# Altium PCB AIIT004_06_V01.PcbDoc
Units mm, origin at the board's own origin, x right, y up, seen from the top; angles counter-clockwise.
Board outline 38.28 x 38.25 mm, 2 copper layers (TopLayer, BottomLayer); 78 components, 44 nets, 236 pads, 151 vias.
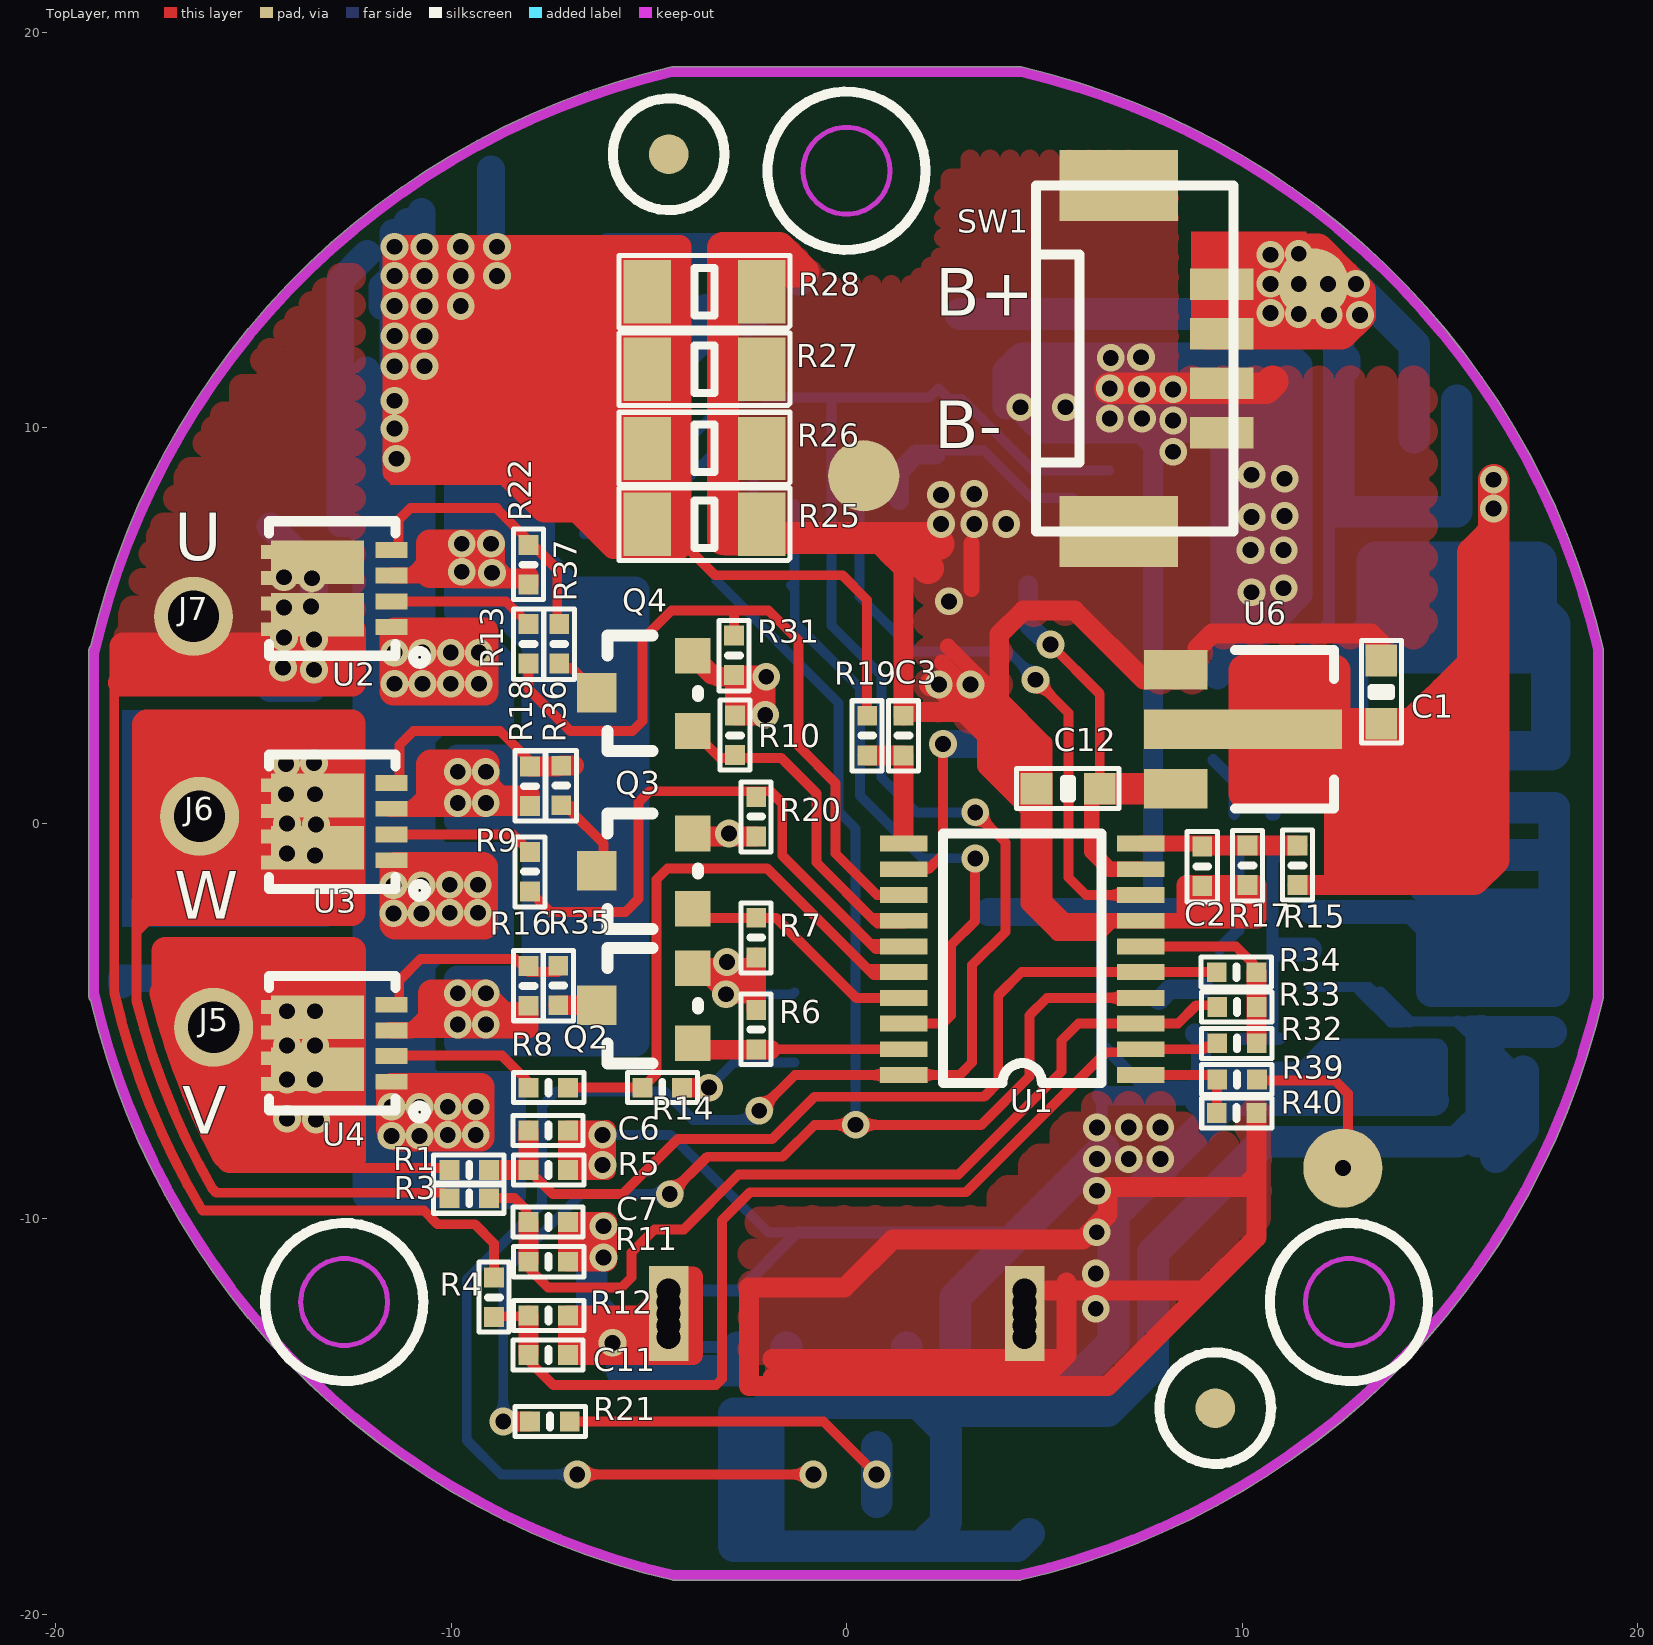
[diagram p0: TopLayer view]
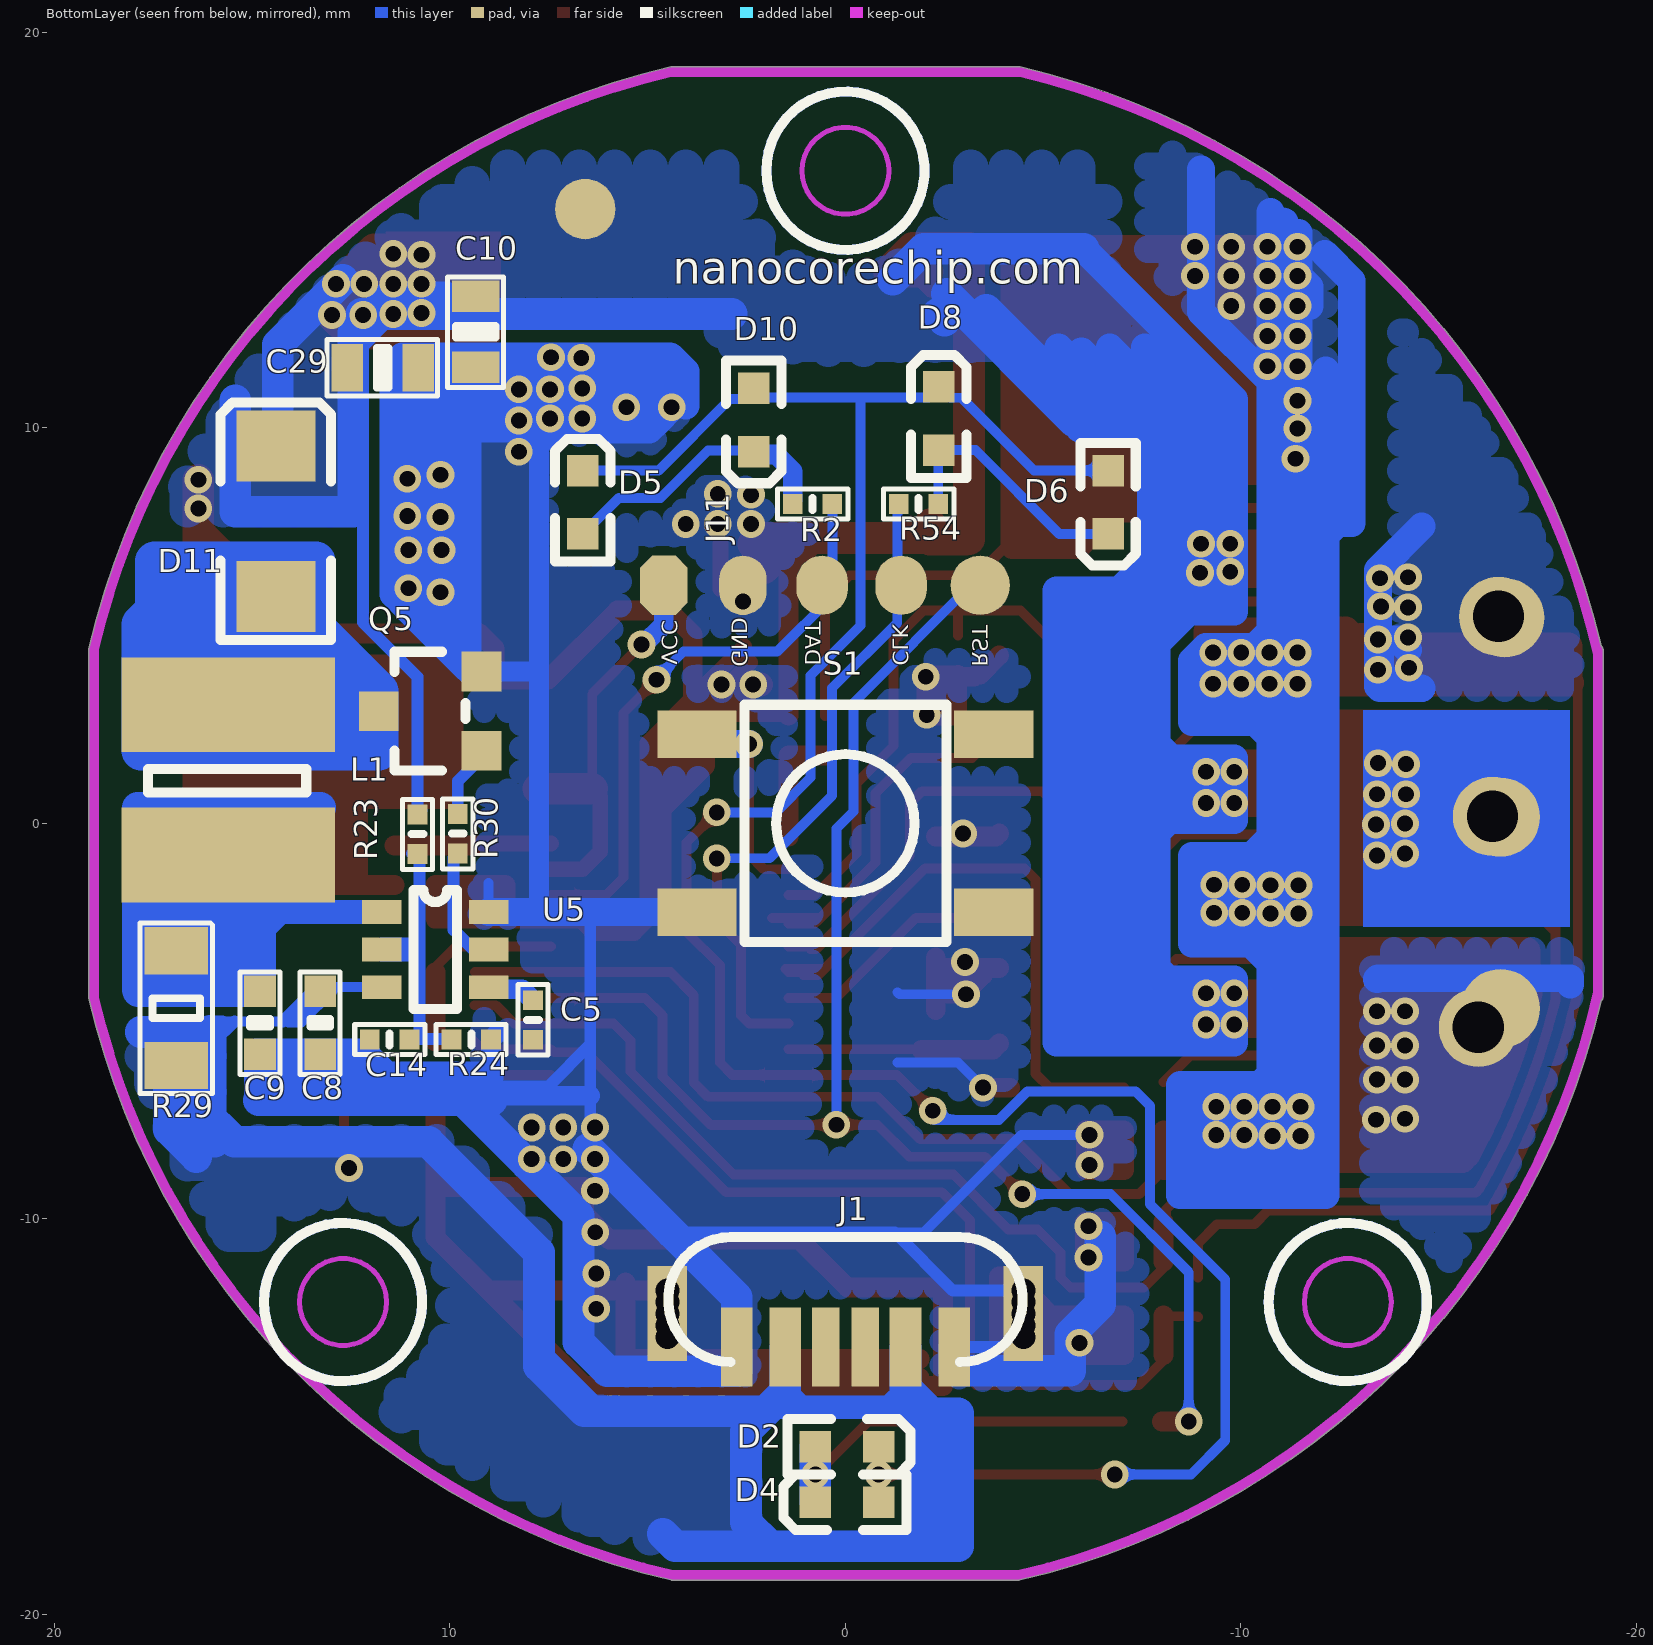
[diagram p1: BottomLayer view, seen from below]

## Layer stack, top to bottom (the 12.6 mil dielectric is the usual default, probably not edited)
TopSolder: solder mask 0.0102, Solder Resist, Dk 3.5
TopLayer: signal copper 0.0356
Dielectric1: dielectric 0.32, FR-4, Dk 4.8
BottomLayer: signal copper 0.0356
BottomSolder: solder mask 0.0102, Solder Resist, Dk 3.5

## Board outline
-19.153,-4.387 -19.153,4.224 cw(c-19.03,4.257) -19.154,4.285 -19.153,4.387 cw(c-19.025,4.387) -19.108,4.483 cw(c0,0) -4.415,19.124 cw(c-4.387,19) -4.379,19.127 4.38,19.127 cw(c4.387,19) 4.415,19.124 cw(c0,0) 19.124,4.415 cw(c19,4.387) 19.128,4.387 19.127,-4.387 cw(c19.001,-4.387) 19.126,-4.405 cw(c19,-4.389) 19.124,-4.417 cw(c0,0) 4.415,-19.124 cw(c4.387,-19) 4.379,-19.127 -4.379,-19.127 cw(c-4.387,-19) -4.415,-19.124 cw(c0,0) -19.108,-4.483 cw(c-19.025,-4.387)

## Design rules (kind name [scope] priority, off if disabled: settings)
Clearance Clearance_1 [All] p1: gap=0.2 ignorepadtopadclearanceinfootprint=FALSE
Clearance [All] p2: gap=0.2 ignorepadtopadclearanceinfootprint=FALSE
ComponentClearance [All] p1 off: gap=0.254 collisioncheckmode=3 verticalgap=0.254 showdistances=FALSE
DiffPairsRouting [All] p1: maxlimit=0.254 minlimit=0.254 mostfreqgap=0.254 substack1={E679878C-6FF9-4B68-BEEA-18ABA4E6F12B} toplayer_{e679878c-6ff9-4b68-beea-18aba4e6f12b}_minwidth=0.381 toplayer_{e679878c-6ff9-4b68-beea-18aba4e6f12b}_maxwidth=0.381 toplayer_{e679878c-6ff9-4b68-beea-18aba4e6f12b}_prefwidth=0.381 bottomlayer_{e679878c-6ff9-4b68-beea-18aba4e6f12b}_minwidth=0.381 bottomlayer_{e679878c-6ff9-4b68-beea-18aba4e6f12b}_maxwidth=0.381 bottomlayer_{e679878c-6ff9-4b68-beea-18aba4e6f12b}_prefwidth=0.381 toplayer_minwidth=0.381 toplayer_maxwidth=0.381 toplayer_prefwidth=0.381 bottomlayer_minwidth=0.381 bottomlayer_maxwidth=0.381 bottomlayer_prefwidth=0.381 substack2={777710C2-B5EE-40DD-8915-E3704981BEB1} toplayer_{777710c2-b5ee-40dd-8915-e3704981beb1}_minwidth=0.381 toplayer_{777710c2-b5ee-40dd-8915-e3704981beb1}_maxwidth=0.381 toplayer_{777710c2-b5ee-40dd-8915-e3704981beb1}_prefwidth=0.381 bottomlayer_{777710c2-b5ee-40dd-8915-e3704981beb1}_minwidth=0.381 bottomlayer_{777710c2-b5ee-40dd-8915-e3704981beb1}_maxwidth=0.381 bottomlayer_{777710c2-b5ee-40dd-8915-e3704981beb1}_prefwidth=0.381 substack3={E62929A6-BD46-4539-BCB2-BD57CF14018D} toplayer_{e62929a6-bd46-4539-bcb2-bd57cf14018d}_minwidth=0.381 toplayer_{e62929a6-bd46-4539-bcb2-bd57cf14018d}_maxwidth=0.381 toplayer_{e62929a6-bd46-4539-bcb2-bd57cf14018d}_prefwidth=0.381 bottomlayer_{e62929a6-bd46-4539-bcb2-bd57cf14018d}_minwidth=0.381 bottomlayer_{e62929a6-bd46-4539-bcb2-bd57cf14018d}_maxwidth=0.381 bottomlayer_{e62929a6-bd46-4539-bcb2-bd57cf14018d}_prefwidth=0.381 substack4={0F8194CC-C03F-4DEF-AB20-F6559DEB5A2B} toplayer_{0f8194cc-c03f-4def-ab20-f6559deb5a2b}_minwidth=0.381 toplayer_{0f8194cc-c03f-4def-ab20-f6559deb5a2b}_maxwidth=0.381 toplayer_{0f8194cc-c03f-4def-ab20-f6559deb5a2b}_prefwidth=0.381 bottomlayer_{0f8194cc-c03f-4def-ab20-f6559deb5a2b}_minwidth=0.381 bottomlayer_{0f8194cc-c03f-4def-ab20-f6559deb5a2b}_maxwidth=0.381 bottomlayer_{0f8194cc-c03f-4def-ab20-f6559deb5a2b}_prefwidth=0.381 substack5={8A69428B-D5D5-4660-97CD-E7EB869ACB37} toplayer_{8a69428b-d5d5-4660-97cd-e7eb869acb37}_minwidth=0.381 toplayer_{8a69428b-d5d5-4660-97cd-e7eb869acb37}_maxwidth=0.381 toplayer_{8a69428b-d5d5-4660-97cd-e7eb869acb37}_prefwidth=0.381 bottomlayer_{8a69428b-d5d5-4660-97cd-e7eb869acb37}_minwidth=0.381 bottomlayer_{8a69428b-d5d5-4660-97cd-e7eb869acb37}_maxwidth=0.381 bottomlayer_{8a69428b-d5d5-4660-97cd-e7eb869acb37}_prefwidth=0.381 maxuncoupledlength=12.7
FabricationTestPointUsage TestPointUsage [All] p1: valid=0 allowmultiple=FALSE
FabricationTestpoint Testpoint [All] p1: side=3 testpointundercomponent=TRUE minsize=1.016 maxsize=2.54 preferedsize=1.524 minholesize=0.508 maxholesize=1.016 preferedholesize=0.813 testpointgrid=0.025 allowsidetop=TRUE allowsidebottom=TRUE usegrid=TRUE gridtolerance=0
Height [All] p1 off: minheight=0 maxheight=25.4 prefheight=12.7
PolygonConnect [All] p1: connectstyle=Direct reliefconductorwidth=0.254 reliefentries=4 polygonreliefangle="90 Angle" airgapwidth=0.254
RoutingVias [All] p1: holewidth=0.711 width=1.27 viastyle="Through Hole" minholewidth=0.711 minwidth=1.27 maxholewidth=0.711 maxwidth=1.27
SolderMaskExpansion [All] p1: expansion=0.102 istentingtop=FALSE
Width [All] p1: maxlimit=8 minlimit=0.25 preferedwidth=0.8 substack1={E679878C-6FF9-4B68-BEEA-18ABA4E6F12B} substack2={777710C2-B5EE-40DD-8915-E3704981BEB1} substack3={E62929A6-BD46-4539-BCB2-BD57CF14018D} substack4={0F8194CC-C03F-4DEF-AB20-F6559DEB5A2B} substack5={8A69428B-D5D5-4660-97CD-E7EB869ACB37}
25 further rules are at their usual default settings.

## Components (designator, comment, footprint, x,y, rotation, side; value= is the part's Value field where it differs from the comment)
C1 "104" 0603M 13.52,4.12 r0 top
C2 "104" 0402M 8.992,-0.584 r0 top
C3 "102" 0402M 1.44,2.72 r0 top
C5 "105" 0402M 7.899,-5.47 r0 bottom
C6 "NC" 0402M -7.04,-7.76 r270 top
C7 "NC" 0402M -7.04,-10.08 r270 top
C8 "106" 0603M 13.28,-5.84 r0 bottom
C9 "106" 0603M 14.8,-5.84 r0 bottom
C10 "10uF" 0805MS 9.35,11.53 r0 bottom
C11 "NC" 0402M -7.04,-13.44 r270 top
C12 "106" 0603M 4.8,0.88 r90 top
C14 "100pF" 0402M 12.024,-5.461 r90 bottom
C29 "10uF" 0805MS 12.598,11.52 r90 bottom
D2 "GREEN" SMD_LED_0603 -0.04,-15.76 r180 bottom
D4 "RLED" SMD_LED_0603 -0.04,-17.16 r0 bottom
D5 "GREEN" SMD_LED_0603 6.64,8.12 r90 bottom locked
D6 "GREEN" SMD_LED_0603 -6.64,8.12 r270 bottom locked
D8 "GREEN" SMD_LED_0603 -2.362,10.236 r90 bottom
D10 "GREEN" SMD_LED_0603 2.32,10.2 r270 bottom
D11 "SS34" SMA 14.4,7.64 r90 bottom
J1 "TYPE-C" TYPE-C-CV 0,-12.04 r90 bottom
J5 "W" TP1 -16.002,-5.156 r0 top
J6 "V" TP1 -16.358,0.178 r0 top
J7 "U" TP1 -16.51,5.232 r0 top
J11 "con16" SIP6-2.0 4.591,6.02 r180 bottom
L1 "4.7UH" L_CD58 15.6,-0.8 r0 bottom
Q2 "2N7002" SOT-23 -3.886,-5.563 r90 top
Q3 "2N7002" SOT-23 -3.886,-2.159 r90 top
Q4 "2N7002" SOT-23 -3.886,2.337 r90 top
Q5 "KS3400" SOT23L 11.8,2.84 r180 bottom
R1 "6.2K" 0402M -9.04,-8.76 r270 top
R2 "1K" 0402M 1.33,8.077 r90 bottom
R3 "6.2K" 0402M -9.04,-9.474 r270 top
R4 "6.2K" 0402M -8.915,-12.481 r180 top
R5 "1K" 0402M -8.04,-8.76 r90 top
R6 "5.1K" 0402M -2.286,-5.715 r180 top
R7 "5.1K" 0402M -2.286,-2.388 r0 top
R8 "47R" 0402M -8.04,-6.68 r90 top
R9 "47R" 0402M -8,-0.72 r0 top
R10 "5.1K" 0402M -2.819,1.727 r180 top
R11 "1K" 0402M -8.04,-11.08 r90 top
R12 "1K" 0402M -8.04,-12.44 r90 top
R13 "47R" 0402M -8.04,5.04 r0 top
R14 "5.1K" 0402M -5.16,-6.68 r90 top
R15 "1M" 0402M 11.4,-1.56 r180 top
R16 "5.1K" 0402M -8.04,-4.608 r180 top
R17 "100K" 0402M 10.135,-0.559 r0 top
R18 "5.1K" 0402M -8,0.44 r180 top
R19 "1K" 0402M 0.52,2.72 r0 top
R20 "5.1K" 0402M -2.286,0.67 r0 top
R21 "1K" 0402M -8,-15.12 r90 top
R22 "5.1K" 0402M -8.04,6.04 r180 top
R23 "953K" 0402M 10.82,0.229 r180 bottom
R24 "100K" 0402M 8.957,-5.461 r270 bottom
R25 "0.1" 1206M -5.04,7.56 r0 top
R26 "0.1" 1206M -5.04,9.48 r0 top
R27 "0.1" 1206M -5.04,11.48 r0 top
R28 "0.1" 1206M -5.04,13.44 r0 top
R29 "0.1" 1206M 16.92,-6.12 r90 bottom
R30 "47R" 0402M 9.8,0.24 r180 bottom
R31 "5.1K" 0402M -2.845,4.75 r0 top
R32 "6.2K" 0402M 10.37,-5.56 r270 top
R33 "6.2K" 0402M 10.37,-4.64 r270 top
R34 "6.2K" 0402M 10.36,-3.76 r270 top
R35 "47R" 0402M -7.29,-3.597 r0 top
R36 "47R" 0402M -7.214,1.457 r0 top
R37 "47R" 0402M -7.264,5.04 r0 top
R39 "1K" 0402M 10.373,-6.477 r270 top
R40 "5.1K" 0402M 9.36,-7.32 r90 top
R54 "1K" 0402M -1.346,8.077 r90 bottom
S1 "SW-PB" 6MM-BTNSMD 0,0 r180 bottom locked
SW1 "DP_1*5" CH1.25_4PVH 9.483,13.629 r270 top
U1 "ATM8F8040" SSOP20 7.64,-6.36 r180 top
U2 "KS3640" DFN-8_3333 -13.031,5.911 r90 top
U3 "KS3640" DFN-8_3333 -13.031,0.018 r90 top
U4 "KS3640" DFN-8_3333 -13.031,-5.585 r90 top
U5 "CN3300" SOT23-6 11.72,-2.24 r180 bottom
U6 "HT7550" SOT89 8.32,3.88 r270 top

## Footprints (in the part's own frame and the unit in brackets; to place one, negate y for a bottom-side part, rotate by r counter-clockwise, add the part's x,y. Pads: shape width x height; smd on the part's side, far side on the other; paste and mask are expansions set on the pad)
6MM-BTNSMD [mm]
  rect 2x1.2 smd: 1(-3.75,2.25) 2(-3.75,-2.25) 3(3.75,-2.25) 4(3.75,2.25)
  silkscreen extent -2.55,-3 2.55,3
0402M [mm]
  rect 0.5x0.5 smd: 1(0,0) 2(0,-1)
  silkscreen extent -0.38,-1.4 0.38,0.38
0603M [mm]
  rect 0.8x0.8 smd: 1(0,0) 2(0,-1.6)
  silkscreen extent -0.51,-2.08 0.51,0.51
0805MS [mm]
  rect 1.2x0.8 smd: 1(0,0) 2(0,-1.8)
  silkscreen extent -0.71,-2.29 0.71,0.51
1206M [mm]
  rect 1.2x1.6 smd: 1(0,0) 2(2.9,0)
  silkscreen extent -0.71,-0.91 3.61,0.91
CH1.25_4PVH [mm]
  rect 1.8x3 smd: 0(-2.5,-2.6) 0(6.25,-2.6)
  rect 0.8x1.6 smd: 1(0,0) 2(1.25,0) 3(2.5,0) 4(3.75,0)
  silkscreen extent -2.5,-4.7 6.25,0.3
DFN-8_3333 [mm] "npmos"
  rect 0.4x0.8 smd: 1(-0.948,-1.525) 2(-0.298,-1.525) 3(0.352,-1.525) 4(1.002,-1.525)
  rect 0.35x0.5 smd: 5(0.947,1.525) 6(0.297,1.525) 7(-0.353,1.525) 8(-1.003,1.525)
  rect 1.1x2.35 smd: 9(-0.633,0.345) 10(0.687,0.345)
  silkscreen extent -1.87,-2.4 1.73,1.58
L_CD58 [mm]
  rect 5.4x2.4 smd: 1(0,0) 2(0,-3.8)
  silkscreen extent -1.97,-2.18 2.03,-1.58
SIP6-2.0 [mm]
  oct 1.2x1.5 smd: 1(0,0)
  oval 1.2x1.5 smd: 2(2,0)
  oval 1.3x1.5 smd: 3(4,0) 4(6,0)
  round 1.5 smd: 5(8,0)
SMA [mm]
  rect 1.8x2 smd: 1(1.9,0) 2(-1.9,0)
  silkscreen extent -3,-1.4 3,1.4
SMD_LED_0603 [mm]
  rect 0.8x0.8 smd: 1(0.8,0) 2(-0.8,0)
  silkscreen extent -1.5,-0.7 1.6,0.7
SOT23-6 [mm]
  rect 1x0.6 smd: 1(0,0) 2(0,-0.95) 3(0,-1.9) 4(2.7,-1.9) 5(2.7,-0.95) 6(2.7,0)
  silkscreen extent 0.8,-2.45 1.9,0.55
SOT23L [mm]
  rect 1x1 smd: 1(2.6,-1) 2(2.6,1) 3(0,0)
  silkscreen extent 0.4,-1.5 2.2,1.5
SOT89 [mm]
  rect 1x1.6 smd: 1(0,0) 3(3,0)
  rect 1x5 smd: 2(1.5,1.7)
  silkscreen extent -0.5,1.5 3.5,4
SOT-23 [mm]
  rect 0.9x0.9 smd: 1(0,0) 2(1.905,0)
  rect 1x1 smd: 3(0.965,2.432)
  silkscreen extent -0.51,-0.13 2.41,2.16
SSOP20 [mm]
  rect 1.2x0.4 smd: 1(0.2,0) 2(0.2,-0.65) 3(0.2,-1.3) 4(0.2,-1.95) 5(0.2,-2.6) 6(0.2,-3.25) 7(0.2,-3.9) 8(0.2,-4.55) 9(0.2,-5.2) 10(0.2,-5.85) 11(6.2,-5.85) 12(6.2,-5.2) 13(6.2,-4.55) 14(6.2,-3.9) 15(6.2,-3.25) 16(6.2,-2.6) 17(6.2,-1.95) 18(6.2,-1.3) 19(6.2,-0.65) 20(6.2,0)
  silkscreen extent 1.2,-6.1 5.2,0.2
TP1 [mm]
  round 2 hole 1.3: 1(0,0)
TYPE-C-CV [mm]
  rect 2x0.8 smd: 1(-1.2,-2.75) 2(-1.2,-1.52) 5(-1.2,1.52) 6(-1.2,2.75)
  round 0.6 hole 0.6: 1(-0.951,-4.5) 1(-0.65,-4.5) 1(-0.06,-4.5) 1(0.23,-4.5) 6(-0.951,4.5) 6(-0.65,4.5) 6(-0.06,4.5) 6(0.23,4.5)
  rect 2.4x1 hole 0.6: 1(-0.355,-4.5) 6(-0.355,4.5)
  rect 2x0.7 smd: 3(-1.2,-0.5) 4(-1.2,0.5)
  silkscreen extent -1.58,-4.48 1.58,4.48

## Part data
C1 C2 C3 C5 C6 C7 C8 C9 C10 C11 C12 C14: library part CAP, "CAP"
C29: library part DIP_ECAP, "直插电解电容"
D2 D4 D5 D6 D8 D10: library part LED
D11: library part DIODE
J1: library part 单排针2.54mm-6P
J5 J6 J7: library part testpoint
J11: library part 单排针2.54mm-5P
L1: library part Inductor
Q2 Q3 Q4 Q5: library part NMOS-2, "N-Channel Power MOSFET"
R1 R2 R3 R4 R5 R6 R7 R8 R9 R10 R11 R12 R13 R14 R15 R16 R17 R18 R19 R20 R21 R22 R23 R24 R25 R26 R27 R28 R29 R30 R31 R32 R33 R34 R35 R36 R37 R39 R40 R54: library part R
S1: library part MT_KT_D_6*6, "（贴片）按键"
SW1: "单排5芯接插件"
U2 U3 U4: library part KS4606
U6: "立创物料号：C59200"

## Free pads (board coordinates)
  round 2 smd far side: 0(-16.667,5.2) 0(-16.561,-4.68) 0(-16.56,0.16)
  round 1.8 smd: 1(0.432,8.788) 1(11.798,13.64)
  round 1 smd: 2(-4.496,16.916) 2(9.322,-14.783)
  round 2 smd: 2(12.548,-8.712)
  round 1.524 smd far side: 3(6.58,15.53)

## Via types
v1: diameter 0.7, hole 0.4, TopLayer to BottomLayer, tented both sides, 151 vias

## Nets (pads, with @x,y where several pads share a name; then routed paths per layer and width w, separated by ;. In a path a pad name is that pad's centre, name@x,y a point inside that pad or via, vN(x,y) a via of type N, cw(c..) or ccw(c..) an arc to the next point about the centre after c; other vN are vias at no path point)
+5: C12.2 J11.1 U1.9 U6.3 | length 10.1
  TopLayer w0.25: v1(5.156,4.521) 6.4,3.277 C12.2
  TopLayer w0.4: C12.2@6.198,0.686 6.198,-0.711 6.646,-1.16 U1.9
  TopLayer w0.8: C12.2 U6.3@7.763,0.88
  BottomLayer w0.5: J11.1 4.591,5.032 5.102,4.521 v1(5.156,4.521)
AVERAGE: R32.1 R33.1 R34.1 U1.6 | length 4.9
  TopLayer w0.25: U1.6 9.841,-3.11 R34.1@10.36,-3.629
  TopLayer w0.5: R32.1@10.36,-5.512 10.36,-4.597 R34.1
CHECK_VIN: R39.2 R40.1 U1.1 | length 2.8
  TopLayer w0.25: U1.1 9.256,-6.36 R39.2 9.366,-6.483 9.366,-7.314 R40.1
GND: C1.1 C2.2 C3.1 C5.1 C6.1 C7.1 C8.1 C9.1 C10.1 C11.1 C12.1 C14.1 C29.2 J1.1 J1.6 J11.2 pad.1@0.432,8.788 Q2.2 Q3.2 Q4.2 Q5.2 R5.2 R6.2 R7.2 R10.2 R11.2 R12.2 R14.2 R17.2 R20.2 R24.1 R25.2 R26.2 R27.2 R28.2 R31.2 R40.2 S1.2 S1.3 SW1.0 SW1.3 SW1.4 U1.7 U5.6 U6.1 | length 361
  TopLayer w0.3: R28.2 -1.635,13.945 -1.483,14.097
  TopLayer w0.4: 2.413,4.064 4.597,1.88 4.597,1.245 4.597,0.483 4.597,-2.032 5.334,-2.769 6.375,-2.769 6.684,-2.46 ; 2.565,4.47 3.861,3.175 5.004,2.032 5.004,-1.956 ; 3.16,5.92 3.16,7.083 ; 4.8,2.19 4.8,1.042 C12.1 4.8,0.28 4.8,-1.752 5.004,-1.956 ; 10.385,-2.46 U1.7 6.684,-2.46 ; 5.004,-1.956 5.508,-2.46 6.684,-2.46
  TopLayer w0.5: -6.756,-7.785 -6.756,-7.874 -6.756,-8.76 ; -6.706,-10.846 -6.706,-10.08 ; v1@-6.414,-8.745 -6.414,-7.874 v1@-6.414,-7.76 ; v1@-6.405,-11.053 v1@-6.405,-10.08 ; v1@-6.083,-7.76 v1@-6.414,-7.76 ; v1@-6.074,-7.75 -6.074,-8.76 -6.756,-8.76 ; v1@-6.065,-11.08 R11.2 C7.1 -6.706,-10.08 ; v1@-6.049,-11.071 -6.049,-10.08 v1@-6.405,-10.08 ; J1.1@-4.851,-12.751 -7.04,-12.751 ; J1.1@-4.826,-12.065 -5.201,-12.44 ; J1.1@-4.641,-13.132 v1(-5.918,-13.132) -7.04,-13.132 ; J1.1@-4.545,-12.44 -5.201,-12.44 ; J1.1@-4.245,-11.452 -3.883,-11.452 -3.883,-13.44 C11.1 -7.04,-13.132 ; R14.2 v1(-3.48,-6.68) ; Q2.2 Q2.2@-3.48,-3.658 ; Q3.2 -3.81,-0.33 R20.2 ; Q4.2 -3.404,3.759 -3.302,3.759 -3.251,3.708 R31.2@-2.819,3.708 ; R31.2 R31.2@-2.842,3.747 ; R6.2 -2.286,-4.262 ; R7.2 -2.286,-3.81 ; -1.88,-14.021 4.978,-14.021 5.563,-13.437 5.563,-11.81 ; -1.88,-13.538 5.309,-13.538 ; 0.787,7.087 1.44,6.434 C3.1 1.539,2.819 3.023,2.819 3.643,2.819 ; J1.6@4.5,-11.81 5.563,-11.81 ; 4.597,1.88 4.597,2.159 3.861,2.896 3.861,3.175 3.861,4.775 4.47,5.385 5.766,5.385 7.518,3.632 8.865,3.632 8.865,4.42 9.246,4.801 13.259,4.801 13.37,4.689 ; 5.563,-11.608 5.563,-11.81 ; 8.596,-2.267 8.596,-1.56 8.998,-1.56 9.37,-1.56 10.36,-1.56 10.36,-2.384 ; 9.37,-1.559 R17.2 ; R40.2 10.36,-8.893 ; 13.487,4.572 13.37,4.689 ; C1.1 13.37,4.27 13.37,4.689 ; -7.04,-13.132 -7.04,-12.751 ; -7.04,-12.751 R12.2 -5.201,-12.44 ; -6.756,-8.76 R5.2 C6.1 v1@-6.414,-7.76 ; -6.706,-10.08 v1@-6.405,-10.08 ; Q2.2@-3.48,-3.658 -3.48,-3.832 -3.048,-4.264 v1(-3.048,-4.318) v1@-3.035,-4.305 ; Q2.2@-3.48,-3.658 v1@-3.035,-3.658 ; v1@-3.035,-4.305 -2.682,-4.305 ; v1@-3.035,-4.305 v1@-3.035,-3.658 ; v1@-3.035,-3.658 v1@-2.924,-3.658 ; v1@-3.035,-3.658 -3.035,-3.518 v1(-3.023,-3.505) -3.023,-3.559 v1@-2.924,-3.658 ; v1@-2.924,-3.658 -2.682,-3.9 -2.682,-4.305 ; v1@-2.924,-3.658 -2.438,-3.658 -2.286,-3.81 ; R31.2@-2.842,3.747 -2.432,3.747 ; R31.2@-2.842,3.747 -2.819,3.724 R31.2@-2.819,3.708 ; R31.2@-2.819,3.708 -2.432,3.708 ; R31.2@-2.819,3.708 R10.2 -2.446,2.727 ; -2.682,-4.305 -2.329,-4.305 -2.286,-4.262 ; -2.446,2.727 -2.073,2.727 v1(-2.057,2.743) -2.045,2.756 v1@-2.045,3.708 ; -2.446,2.727 -2.432,2.742 -2.432,3.708 ; -2.432,3.708 -2.432,3.747 ; -2.432,3.708 v1@-2.045,3.708 ; -2.432,3.747 -2.07,3.747 v1@-2.045,3.721 ; -2.286,-4.262 -2.286,-3.81 ; v1@-2.045,3.708 v1@-2.045,3.721 ; v1@-2.045,3.708 v1(-2.032,3.708) v1@-2.045,3.721 ; 5.563,-11.81 9.018,-11.81 ; 9.018,-11.81 6.604,-14.224 -2.464,-14.224 -2.464,-11.735 -0.051,-11.735 1.168,-10.516 5.969,-10.516 6.604,-9.881 6.604,-9.195 10.058,-9.195 10.36,-8.893 ; 9.018,-11.81 10.36,-10.468 10.36,-8.893
  TopLayer w0.6: v1@2.134,3.512 2.33,3.512 2.331,3.511 3.023,2.819 3.602,2.24 ; 4.8,0.28 4.597,0.483 3.602,1.478 3.602,2.24 ; C12.1@4.8,1.042 4.597,1.245 3.602,2.24
  TopLayer w0.7: J1.6@4.5,-11.835 J1.6@4.648,-11.983
  TopLayer w0.8: -3.124,7.188 -3.124,11.48 -3.124,14.554 -1.702,14.554 -1.092,13.945 -1.635,13.945 R28.2@-2.083,13.945 ; -3.042,7.169 -2.14,7.169 R25.2@-2.14,7.414 ; R25.2 R25.2@-2.14,7.414 ; 2.057,6.452 1.295,7.214 ; 2.333,7.063 2.182,7.214 1.295,7.214 ; v1(6.655,10.998) 10.592,10.998 10.77,11.176 ; SW1.3 SW1.3@9.881,11.129 ; R25.2@-2.14,7.414 -1.94,7.214 1.295,7.214
  BottomLayer w0.25: v1(-6.172,-7.874) -4.445,-7.874 -1.979,-10.34 -1.247,-10.34 ; v1(-3.48,-6.68) -2.845,-6.045 -1.321,-6.045 ; v1(-3.048,-4.318) -1.372,-4.318 -1.321,-4.267 ; U5.6 9.02,-1.502
  BottomLayer w0.3: J1.1@-4.743,-13.24 J1.1@-2.75,-13.24 ; J1.1@-4.5,-11.81 -2.717,-11.81 -1.247,-10.34 4.392,-10.34 ; v1@6.452,-8.179 6.452,-7.688 6.452,-6.883 6.452,-5.588 ; 6.452,-2.24 6.452,-5.588 ; 10.64,9.28 10.77,9.28 11.345,9.28 ; 12.649,-6.655 12.173,-6.655 12.073,-6.655 11.514,-6.655 9.779,-6.655 9.661,-6.655 9.04,-6.655 7.518,-6.655 6.452,-5.588
  BottomLayer w0.5: 6.452,-6.883 7.518,-6.883 9.04,-6.883 9.661,-6.883 9.779,-6.883 11.514,-6.883 12.073,-6.883 12.649,-6.883 13.538,-6.883 14.91,-6.883 ; 7.493,-2.24 7.747,-1.986 7.747,9.677 7.747,9.982 7.747,10.236 7.747,10.312 v1@7.747,10.444 ; 8.031,3.84 Q5.2 ; R24.1@8.804,-5.309 R24.1 8.957,-6.437 9.04,-6.52 9.779,-6.52 11.514,-6.52 11.893,-6.52 12.073,-6.52 12.173,-6.42 12.473,-6.119 12.7,-5.893
  BottomLayer w0.6: 12.399,-6.27 12.829,-5.84 12.929,-5.74 13.28,-5.74 14.91,-5.74 14.91,-6.325 14.91,-6.883
  BottomLayer w0.7: S1.2@3.586,-2.24 6.452,-2.24 7.493,-2.24 7.747,-2.24 U5.6 ; 4.04,10.56 4.04,11.429 4.394,11.783 4.394,11.227 ; 4.435,11.811 6.68,11.811 7.442,11.811 9.35,11.811 10.798,11.811 11.201,11.811 11.43,11.582 11.43,11.227 11.43,10.668 11.43,10.312 11.43,9.28 11.43,6.909 11.43,5.791 10.846,5.207 10.275,4.635 9.69,4.051 Q5.2@9.373,3.733 ; v1@4.674,10.668 5.537,10.668 6.655,10.668 v1@7.468,10.668 ; 4.928,10.312 5.537,10.312 6.655,10.312 7.468,10.312 7.747,10.312 8.255,10.312 9.55,10.312 10.135,10.312 10.77,10.312 11.024,10.312 11.379,10.312 ; 7.747,9.677 7.468,9.957 6.655,9.957 4.957,9.957 4.765,10.149 v1(4.394,10.52) 4.394,11.227 ; 7.747,9.982 8.255,9.982 9.55,9.982 10.135,9.982 10.77,9.982 11.024,9.982 ; Q5.2@9.55,4.191 9.55,9.728 ; 10.135,4.775 10.135,5.842 10.135,6.909 10.135,7.747 10.135,8.814 10.135,9.703 ; 10.77,5.283 10.77,5.944 10.77,6.909 10.77,7.772 10.77,8.814 10.77,9.28 10.77,9.728 ; 11.328,11.227 10.798,11.227 9.35,11.227 8.255,11.227 7.468,11.227 6.655,11.227 4.394,11.227 ; v1@7.468,10.668 7.747,10.668 ; v1@7.468,10.668 7.747,10.668 ; 7.747,10.668 v1@8.255,10.668 ; v1@8.255,10.668 11.405,10.668 v1@8.255,10.668
  BottomLayer w0.8: -6.441,-10.433 -6.441,-10.973 -6.441,-12.151 -5.679,-12.913 -5.679,-13.836 -2.75,-13.836 J1.1@-2.75,-13.24 ; v1@6.502,-8.23 6.288,-8.444 4.392,-10.34 2.75,-11.982 2.75,-13.24 2.75,-13.85 6.013,-13.85 6.747,-13.116 6.747,-11.379 6.747,-9.915 8.054,-8.609 9.661,-7.002 ; 8.941,-7.002 9.661,-7.002 ; 9.04,-6.42 9.779,-6.42 11.614,-6.42 ; 9.779,-6.883 9.661,-7.002 ; 11.514,-6.52 11.614,-6.42 ; 13.538,-6.325 14.8,-6.325 ; 14.749,-6.655 13.538,-6.655 12.649,-6.655 12.884,-6.42 ; C9.1 C8.1 ; 14.825,-7.002 13.538,-7.002 12.649,-7.002 12.073,-7.002 11.514,-7.002 9.661,-7.002 ; 11.614,-6.42 11.793,-6.241 11.893,-6.141 12.194,-5.84 12.829,-5.84 C8.1 ; 11.614,-6.42 12.173,-6.42 12.473,-6.42 12.884,-6.42 ; 12.884,-6.42 13.28,-6.024 C8.1
  other v1: 6.299,-12.268 6.299,-11.379 -6.147,-10.973 6.325,-10.338 -6.147,-10.185 6.333,-9.288 -6.172,-8.636 6.333,-8.488 7.133,-8.488 7.933,-8.488 6.333,-7.688 7.133,-7.688 7.933,-7.688 -2.972,-0.254 2.333,3.512 3.133,3.512 2.591,5.613 10.236,5.842 11.049,5.944 10.211,6.909 11.049,6.909 2.388,7.569 3.226,7.569 4.039,7.569 10.236,7.747 11.074,7.772 2.388,8.306 3.226,8.331 11.074,8.712 10.236,8.814 8.255,9.398 8.255,10.185 6.655,10.236 7.468,10.236 5.537,10.52 7.468,10.973 8.255,10.973 6.68,11.77 7.442,11.786
IBUS: C3.2 R19.2 U1.11 | length 3
  TopLayer w0.5: R19.2 C3.2 U1.11@1.44,-0.338
KEY: S1.1 U1.12 | length 5.3
  TopLayer w0.25: U1.12 2.066,-1.16 2.438,-0.787 v1@2.438,1.981
  BottomLayer w0.7: v1(2.438,2.007) 3.507,2.007 S1.1
LED_COM: D2.1 D4.2 D5.1 D6.2 D8.1 D10.2 U1.20 | length 65.2
  TopLayer w0.25: v1(-6.807,-16.459) v1(-0.84,-16.459) ; v1(-2.21,-7.264) -1.305,-6.36 U1.20 2.86,-6.36 3.175,-6.045 3.175,-3.581 4.013,-2.743 4.013,-0.483 v1(3.251,0.279)
  BottomLayer w0.25: v1(-6.807,-16.459) -8.738,-16.459 -9.601,-15.596 -9.601,-11.532 -7.696,-9.627 -7.696,-7.137 -7.341,-6.782 -4.597,-6.782 -3.886,-7.493 v1@-2.235,-7.493 ; D6.2 -4.771,8.92 -2.93,10.761 -2.637,10.761 D8.1 -2.096,10.77 -0.384,10.77 2.09,10.77 D10.2 2.595,10.725 2.915,10.725 4.72,8.92 D5.1 ; -0.384,10.693 -0.384,5.007 0.88,3.743 0.88,1.16 1.761,0.279 v1(3.251,0.279)
NetC5_2: C5.2 U5.4 | length 1.3
  BottomLayer w0.5: C5.2 8.18,-4.19 8.97,-4.19 U5.4
NetC9_2: C9.2 L1.1 R29.2 U5.1 | length 20.6
  BottomLayer w0.6: U5.1 14.28,-2.24 14.8,-2.76
  BottomLayer w0.8: L1.1@13.284,0.394 17.894,0.394 L1.1@17.894,-0.8 ; L1.1@14.605,-1.6 14.8,-1.795 14.8,-2.76 C9.2 17.88,-4.24 ; L1.1 L1.1@17.894,-0.8 ; 17.894,-4.204 L1.1@17.894,-0.8
NetC14_2: C14.2 R23.2 R24.2 U5.2 | length 6.5
  BottomLayer w0.3: R24.2 9.97,-5.448 10.935,-5.448 C14.2@10.947,-5.436 ; 10.77,-5.385 10.77,-3.19 R23.2@10.77,-0.87 ; R23.2@10.846,-0.87 R23.2@10.956,-0.76
  BottomLayer w0.6: 10.932,-3.19 U5.2
NetD2_2: D2.2 D4.1 R21.2 | length 9.7
  TopLayer w0.25: R21.2 -0.579,-15.12 v1(0.76,-16.459)
  BottomLayer w0.8: D4.1 D2.2
NetD5_2: D5.2 D10.1 R2.1 | length 7.1
  BottomLayer w0.25: D10.1@2.247,9.327 D10.1 2.343,9.423 3.478,9.423 4.672,8.23 5.73,8.23 D5.2
  BottomLayer w0.5: R2.1@1.33,8.179 1.33,8.899 1.758,9.327 D10.1@2.247,9.327
NetD6_1: D6.1 D8.2 R54.2 | length 6.4
  BottomLayer w0.25: D6.1 -5.405,7.32 -3.289,9.436 D8.2 -2.346,9.42 R54.2@-2.346,8.179
NetD11_2: D11.2 L1.2 Q5.3 | length 25.3
  BottomLayer w1: 11.8,1.84 Q5.3 11.8,3.342 13.386,4.928 13.386,6.629 16.205,6.629 ; 11.857,1.833 L1.2@15.6,1.833 ; 12.7,1.833 12.7,3.795 ; L1.2 L1.2@15.6,1.833 ; 17.457,5.378 17.457,6.629 16.205,6.629 ; L1.2@17.801,1.833 L1.2@15.6,1.833 ; L1.2@17.805,1.88 17.805,5.029 16.205,6.629
NetQ2_3: Q2.3 R35.2 | length 1
  TopLayer w0.5: R35.2 Q2.3
NetQ3_3: Q3.3 R36.2 | length 1.7
  TopLayer w0.25: -6.96,0.44 -6.96,0.305 -6.147,-0.508 Q3.3@-6.147,-0.94
NetQ4_3: Q4.3 R37.2 | length 1.3
  TopLayer w0.25: R37.2@-7.315,4.029 -7.222,3.936 -6.952,3.936 Q4.3
NetQ5_1: Q5.1 R30.1 | length 1.6
  BottomLayer w0.3: Q5.1@9.271,1.6 9.8,1.071 R30.1
NetR8_1: R8.1 U4.2 | length 3.8
  TopLayer w0.25: U4.2@-11.582,-5.872 -8.708,-5.872 R8.1@-8.04,-6.54
NetR9_1: R9.1 U3.2 | length 3.7
  TopLayer w0.25: U3.2@-11.557,-0.284 -8.436,-0.284 -8.35,-0.37 R9.1
NetR13_1: R13.1 U2.2 | length 3.7
  TopLayer w0.25: U2.2 -8.763,5.613 -8.613,5.613 -8.334,5.334 R13.1
NetR16_2: R16.2 R35.1 U4.4 | length 5.2
  TopLayer w0.25: U4.4@-11.582,-4.572 -11.382,-4.572 -11.307,-4.497 -11.307,-3.967 -10.771,-3.43 -9.373,-3.43 -8.37,-3.43 -8.04,-3.76 -8.035,-3.755 -7.295,-3.755 R35.1@-7.29,-3.75
NetR18_2: R18.2 R36.1 U3.4 | length 6
  TopLayer w0.25: U3.4@-11.557,1.016 -11.378,1.016 -11.303,1.091 -11.303,1.981 -10.947,2.337 -8.763,2.337 R18.2@-8,1.574
  TopLayer w0.5: R18.2 R36.1@-7.29,1.44 ; R36.1@-7.214,1.465 -6.884,1.465
NetR19_1: R19.1 R25.1 R26.1 R27.1 R28.1 U2.1 U3.1 U4.1 | length 232
  TopLayer w0.25: R25.1@-5.04,7.25 R25.1 ; -4.216,7.163 -3.327,6.274 -0.102,6.274 0.52,5.652 R19.1
  TopLayer w0.6: v1@-11.5,3.459 v1@-11.5,4.031 ; v1@-11.455,3.275 -11.455,3.326 v1@-11.455,3.605 ; -11.405,8.865 -11.43,8.89 v1(-11.43,9.982) v1(-11.43,10.685) v1(-11.43,11.557) v1(-11.43,12.319) v1(-11.43,13.081) v1(-11.43,13.843) v1(-11.43,14.58) v1(-10.668,14.58) v1(-9.754,14.58) v1(-8.839,14.58) -4.216,14.58 -4.216,7.163 -4.216,6.985 -5.893,6.985 -6.909,8.001 -6.947,8.001
  TopLayer w0.7: U4.1@-11.541,-6.702 v1@-11.541,-7.327 ; U4.1@-11.508,-6.654 -9.249,-6.654 v1@-9.249,-7.644 ; v1@-11.455,3.326 -9.145,3.326 v1@-9.145,4.342 ; v1@-11.455,3.605 -11.455,4.825 -11.429,4.851 -9.145,4.851 v1@-9.145,4.342 ; v1@-11.429,4.342 v1@-9.145,4.342 ; v1@-11.417,-1.283 v1@-9.157,-1.283 ; v1@-11.378,-1.64 v1@-9.5,-1.64 ; -11.204,3.96 -9.5,3.96 ; v1@-9.592,-7.01 -9.909,-7.327 v1@-11.541,-7.327 ; v1@-9.325,-7.619 v1@-9.325,-7.644 ; v1@-9.249,-7.948 -11.325,-7.948 -11.541,-7.732 v1@-11.541,-7.644 ; -7.12,8.517 -7.12,8.56 -7.12,8.96 ; v1@-11.541,-7.644 v1@-9.325,-7.644 ; v1@-11.541,-7.644 v1@-11.541,-7.327 ; v1(-11.455,-2.274) v1(-11.455,-1.563) -11.455,-1.08 -11.442,-1.067 -9.183,-1.067 -9.157,-1.092 v1@-9.157,-1.283 ; v1(-11.455,-2.274) -11.455,-2.552 -11.417,-2.591 -9.157,-2.591 v1@-9.157,-2.274 ; v1(-11.455,-2.274) v1(-10.744,-2.274) v1@-9.157,-2.274 ; v1@-9.325,-7.644 -9.325,-7.923 -9.249,-7.847 v1@-9.249,-7.644 ; v1@-9.325,-7.644 v1@-9.249,-7.644 ; v1@-9.157,-2.274 v1@-9.157,-1.283
  TopLayer w0.8: -10.058,9.627 -9.246,9.627 -8.857,9.238 ; -7.849,8.56 -7.12,8.56 -5.182,8.56 ; -6.947,8.001 -7.62,8.001 -8.857,9.238 ; -6.909,8.001 -6.274,8.001 -6.071,7.798 -6.071,8.111 -6.477,8.517 ; R26.1@-5.282,9.238 -8.857,9.238
  BottomLayer w0.7: -12.141,11.455 -12.141,7.29 ; -12.116,14.405 -12.802,13.719 -12.802,7.595 -12.446,7.595 -12.141,7.29 ; -11.887,-7.327 -11.887,-2.794 ; v1@-11.735,4.318 v1@-11.735,9.982 ; v1@-11.735,13.081 -11.735,13.564 -11.455,13.843 -11.455,14.936 ; v1@-11.709,-7.95 v1@-11.709,-7.874 ; -11.709,-2.616 v1@-11.709,-7.874 ; v1@-11.709,-1.563 -11.709,1.388 ; v1@-11.709,4.318 -11.709,7.214 ; v1@-11.541,-1.563 -11.541,-2.362 -11.925,-2.746 -11.925,-2.794 -12.141,-2.794 ; -11.541,1.388 -11.455,1.473 ; v1(-11.506,-7.163) -11.283,-7.163 -11.1,-6.979 -11.1,1.829 ; v1(-11.455,-1.563) -11.455,1.473 ; v1@-11.455,13.081 -11.455,1.473 ; -11.1,-8.179 v1@-10.821,-8.179 ; v1@-11.1,-7.874 v1@-11.709,-7.874 ; -11.1,15.202 -11.1,1.829 ; v1@-10.744,-8.179 -10.744,-6.35 ; -10.744,-3.099 v1(-10.744,-2.274) v1(-10.744,-1.563) -10.744,-0.356 ; -10.744,2.718 -10.744,4.851 ; -10.744,15.455 -10.744,11.176 ; v1(-10.719,3.531) v1(-10.719,4.318) -10.719,4.724 -10.668,4.775 ; -10.466,-2.821 -10.312,-2.667 -8.764,-2.667 ; -10.274,-6.604 -8.471,-6.604 -8.458,-6.617 -8.458,-6.833 ; -10.225,-1.154 -8.764,-1.154 ; -8.992,16.537 -8.992,12.929 -10.744,11.176 ; -12.141,-7.874 -12.141,-9.398 -8.458,-9.398 -8.458,-6.833 ; -12.141,-7.874 -12.141,-2.794 ; -12.141,-7.874 v1@-11.709,-7.874 ; -12.141,-2.794 -12.141,7.29 ; -11.455,1.473 -11.1,1.829 ; -10.744,-6.35 -10.262,-6.833 -8.458,-6.833 ; -10.744,-6.35 -10.744,-3.531 -10.251,-3.037 -8.764,-3.037 -8.764,-2.667 ; -10.744,-0.356 -10.276,-0.824 -8.764,-0.824 -8.764,-1.154 ; -10.744,-0.356 -10.744,2.184 -10.363,2.565 -8.764,2.565 -8.764,4.115 -9.108,4.459 -10.352,4.459 -10.668,4.775 ; -10.744,4.851 -10.744,11.176 ; -10.744,4.851 -10.668,4.775 ; -8.764,-2.667 -8.764,-1.154
  other v1: -11.506,-7.899 -10.795,-7.899 -10.084,-7.874 -9.373,-7.874 -10.795,-7.163 -10.084,-7.163 -9.373,-7.163 -10.033,-2.261 -9.322,-2.261 -10.033,-1.549 -9.322,-1.549 -11.43,3.531 -10.008,3.531 -9.296,3.531 -11.43,4.318 -10.008,4.318 -9.296,4.318 -11.379,9.22 -10.668,11.557 -10.668,12.319 -10.668,13.081 -9.754,13.081 -10.668,13.843 -9.754,13.843 -8.839,13.843
NetR22_2: R22.2 R37.1 U2.4 | length 7.1
  TopLayer w0.25: U2.4@-11.557,6.903 -11.403,6.903 -11.328,6.978 -11.328,7.671 -11.024,7.976 -8.839,7.976 -8.839,7.95 -7.315,6.426 R37.1@-7.315,5.029
NetR30_2: R30.2 U5.5 | length 2.7
  BottomLayer w0.3: U5.5@9.423,-3.175 9.906,-2.692 9.906,-0.866 R30.2
NRST: J11.5 R21.1 U1.4 | length 39.6
  TopLayer w0.25: v1(-4.47,-9.373) -3.523,-8.426 -1.618,-8.426 -0.813,-7.62 v1(0.229,-7.62) 3.405,-7.62 4.623,-6.402 4.623,-4.851 5.064,-4.41 U1.4
  TopLayer w0.5: v1(-8.68,-15.12) R21.1
  BottomLayer w0.25: v1(-8.68,-15.12) -8.68,-11.347 -6.706,-9.373 v1(-4.47,-9.373) ; J11.5@-3.292,6.137 -0.2,3.045 -0.2,0.3 0.229,-0.129 v1(0.229,-7.62)
PHASEA: J5.1 pad.0@-16.561,-4.68 R1.2 U4.5 U4.6 U4.7 U4.8 U4.9 U4.10 | length 51
  TopLayer w0.25: -12.573,-8.712 -10.088,-8.712 R1.2
  TopLayer w0.7: -17.223,-4.294 -17.223,-3.227 -16.561,-3.227 ; -16.662,-6.062 J5.1@-16.205,-5.605 ; J5.1@-16.561,-5.575 -16.561,-4.394 J5.1@-16.205,-4.394 ; J5.1@-16.368,-5.483 J5.1@-16.205,-5.32 ; -16.205,-6.401 J5.1@-16.205,-5.605 ; J5.1@-16.2,-5.315 J5.1@-16.205,-5.32 ; -16.101,-7.442 -15.847,-7.188 -15.568,-7.468 -14.072,-7.468 -12.522,-7.468 -12.497,-7.442 ; -15.926,-7.267 J5.1@-15.926,-4.597 ; -15.596,-8.484 -12.497,-8.484 -12.497,-7.95 ; -15.57,-7.95 -12.497,-7.95 ; -14.224,-4.216 -14.605,-4.597 J5.1@-15.926,-4.597 ; -14.224,-3.931 -12.497,-3.931 ; -13.081,-7.157 -12.497,-7.157 ; U4.9@-13.081,-6.477 U4.9@-12.497,-6.477 ; U4.10@-13.081,-4.75 U4.10@-12.497,-4.75 ; -13.081,-4.216 -12.497,-4.216 ; -12.498,-3.227 -15.926,-3.227 ; -12.497,-3.226 -12.497,-3.931 ; -16.561,-4.115 -16.561,-3.227 ; -16.561,-4.115 -16.561,-4.216 -16.56,-4.114 -16.561,-4.115 ; -16.561,-4.115 -16.61,-4.163 -16.796,-4.346 -16.841,-4.39 -16.843,-4.677 -16.848,-5.148 -16.852,-5.574 -16.852,-5.6 -16.843,-5.6 J5.1@-16.205,-5.6 ; -16.561,-3.227 -15.926,-3.227 ; J5.1@-16.205,-5.605 J5.1@-16.205,-5.6 ; J5.1@-16.205,-5.605 -16.2,-5.6 J5.1@-16.205,-5.6 ; J5.1@-16.205,-5.6 J5.1@-16.205,-5.32 ; J5.1@-16.205,-5.32 J5.1@-16.205,-4.394 ; J5.1@-16.205,-4.394 J5.1@-15.926,-4.394 ; J5.1@-15.926,-4.597 J5.1@-15.926,-4.394 ; J5.1@-15.926,-4.394 -15.926,-3.227 ; -12.497,-7.95 -12.497,-7.442 ; -12.497,-7.442 -12.497,-7.157 ; -12.497,-7.157 U4.9@-12.497,-6.477 ; U4.9@-12.497,-6.477 -12.497,-4.897 U4.10@-12.497,-4.75 ; U4.10@-12.497,-4.75 -12.497,-4.216 ; -12.497,-4.216 -12.497,-3.931
  TopLayer w0.8: -17.223,-4.294 ccw(c0,0) -16.852,-5.574 ccw(c0,0) -16.843,-5.6 ccw(c0,0) -15.672,-8.333
  BottomLayer w0.7: -18.323,-4.074 -18.323,-3.912 -13.462,-3.912 -13.437,-3.937
  other v1: -13.411,-7.493 -14.148,-7.468 -14.148,-6.477 -13.437,-6.477 -14.148,-5.613 -13.437,-5.613 -14.148,-4.75 -13.437,-4.75
PHASEB: J6.1 pad.0@-16.56,0.16 R3.2 U3.5 U3.6 U3.7 U3.8 U3.9 U3.10 | length 49.6
  TopLayer w0.25: -17.95,-1.947 -17.95,-2.749 ; -17.45,-2.249 -17.95,-2.749 ; R3.2@-10.185,-9.336 -15.936,-9.336 -16.021,-9.25 cw(c0,0) -17.95,-4.476 -17.95,-3.091 -17.95,-2.749
  TopLayer w0.7: -17.719,2.5 -17.719,-2.249 -17.45,-2.249 -12.509,-2.249 U3.10@-12.509,0.85 ; -17.692,2.527 -13.767,2.527 ; -13.602,2.362 -13.767,2.527 ; v1(-13.437,0.737) -12.684,0.737 -12.653,0.706 U3.10@-12.509,0.85 ; -13.767,2.527 -12.509,2.527 U3.10@-12.509,0.85
  BottomLayer w0.7: -17.91,-0.399 -17.119,-1.19 -16.045,-1.19 -15.668,-0.813 v1(-13.437,-0.813) -13.995,-0.813 -14.046,-0.762 v1(-14.148,-0.762) v1(-13.411,-0.025) -13.437,0 v1(-13.437,0.737) -13.437,1.499 v1(-13.462,1.524) -13.466,1.528 -17.101,1.528 -17.91,0.719 -17.91,-0.399
  other v1: -14.148,0 -14.173,0.737 -14.173,1.499
PHASEC: J7.1 pad.0@-16.667,5.2 R4.2 U2.5 U2.6 U2.7 U2.8 U2.9 U2.10 | length 51.8
  TopLayer w0.25: -18.513,4.483 -18.513,3.966 ; -18.212,4.267 -18.513,3.966 ; R4.2 -8.915,-10.617 -9.398,-10.135 -10.339,-10.135 -10.687,-9.787 -10.687,-9.786 -16.286,-9.786 cw(c0,0) -18.513,-4.274 -18.513,3.966
  TopLayer w0.7: -18.323,3.557 -12.495,3.557 -12.495,3.988 ; -18.286,3.988 -12.495,3.988 ; -18.284,4.472 -12.495,4.472 ; v1@-13.349,4.648 -13.109,4.648 -13.044,4.713 -12.929,4.597 -12.649,4.877 -12.495,4.723 ; U2.9@-12.495,4.878 -12.495,4.472 ; -12.495,3.988 -12.495,4.472
  BottomLayer w0.7: -14.567,3.42 -13.928,3.42 ; -14.567,7.513 -13.462,6.408 v1(-13.462,4.648) ; v1@-14.224,4.394 -13.97,4.648 v1@-13.614,4.648 ; -13.928,3.42 v1@-13.513,3.835 ; -13.928,3.42 -13.513,3.42 ; -13.513,3.42 -13.462,3.471 v1(-13.462,3.886) ; -13.513,3.42 v1@-13.513,3.835 ; v1@-13.513,3.835 -13.513,4.597 v1(-13.462,4.648) ; v1@-13.513,3.835 v1(-13.462,3.886) ; v1(-13.462,3.886) v1(-13.462,4.648)
  other v1: -14.249,3.937 -14.224,4.699 -14.224,5.461 -13.538,5.486 -13.513,6.198 -14.224,6.223
PWM_AH: Q2.1 R6.1 U1.19 | length 5.4
  TopLayer w0.25: -1.91,-5.71 U1.19
  TopLayer w0.5: Q2.1 -3.729,-5.72 -2.286,-5.72 -1.92,-5.72
PWM_AL: R8.2 R14.1 U1.16 | length 16.3
  TopLayer w0.25: R8.2 R14.1 -4.808,-6.328 -4.808,-1.422 -4.528,-1.143 -2.007,-1.143 0.61,-3.76 ; 0.559,-3.683 1.517,-3.683 U1.16 1.067,-3.76 0.61,-3.76 ; U1.16@1.067,-3.835 0.686,-3.835 0.61,-3.76
PWM_BH: Q3.1 R7.1 U1.17 | length 6.3
  TopLayer w0.25: Q3.1 -3.658,-2.388 -1.778,-2.388 0.244,-4.41 U1.17
PWM_BL: R9.2 R20.1 U1.15 | length 15.8
  TopLayer w0.25: R9.2 -7.485,-2.235 -5.588,-2.235 -5.258,-1.905 -5.258,0.533 -4.978,0.813 -2.286,0.813 -1.93,0.813 -1.626,0.508 -1.626,-0.813 0.61,-3.048 ; U1.15@0.889,-3.175 0.737,-3.175 0.672,-3.11 ; 0.61,-3.048 0.672,-3.11 ; 0.61,-3.048 1.378,-3.048 U1.15 0.889,-3.11 0.672,-3.11
PWM_CH: Q4.1 R10.1 U1.14 | length 10.4
  TopLayer w0.25: Q4.1 -3.2,1.651 -2.692,1.651 -2.286,1.651 -1.92,1.651 -1.651,1.651 -0.762,0.762 -0.762,-0.991 0.707,-2.46 ; 0.635,-2.388 1.44,-2.388 U1.14@1.854,-2.388 ; 0.707,-2.46 0.78,-2.532 1.44,-2.532 U1.14 0.707,-2.46
PWM_CL: R13.2 R31.1 U1.13 | length 19.2
  TopLayer w0.25: R13.2 -8.04,3.392 -6.985,2.337 -5.41,2.337 -5.156,2.591 -5.156,4.648 -4.424,5.38 -2.845,5.38 ; R31.1 -2.845,5.38 ; U1.13 0.769,-1.81 -0.279,-0.762 -0.279,1.016 -1.219,1.956 -1.219,4.623 -1.976,5.38 -2.845,5.38
SWCLK: J11.4 R54.1 U1.18 | length 17.2
  TopLayer w0.25: U1.18 2.433,-5.06 2.642,-4.851 2.642,-3.073 3.251,-2.464 v1(3.251,-0.889)
  BottomLayer w0.25: J11.4 -1.31,5.921 -1.31,5.069 0.34,3.419 0.34,0.7 1.92,-0.88 3.243,-0.88 v1(3.251,-0.889) ; J11.4@-1.321,6.02 R54.1@-1.321,8.077
SWDAT: J11.3 R2.2 U1.8 | length 15
  TopLayer w0.25: v1(4.775,3.632) 5.613,2.794 5.613,-1.372 6.052,-1.81 U1.8
  BottomLayer w0.25: R2.2 0.33,5.74 1.724,4.347 3.615,4.347 3.618,4.343 4.089,4.343 4.775,3.658 v1(4.775,3.632)
UA: C6.2 R1.1 R5.1 R34.2 U1.5 | length 23.4
  TopLayer w0.25: R5.1 -7.427,-9.373 -5.664,-9.373 -4.42,-8.128 -4.267,-7.976 -1.88,-7.976 -0.813,-6.909 3.48,-6.909 3.835,-6.553 3.835,-4.343 4.419,-3.76 U1.5 R34.2 ; C6.2 C6.2@-8.04,-7.634
  TopLayer w0.5: R1.1 R5.1 C6.2
UB: C7.2 R3.1 R11.1 R33.2 U1.3 | length 23.9
  TopLayer w0.25: R3.1@-9.017,-9.474 -8.392,-9.474 -8.103,-9.764 -8.103,-10.017 C7.2 ; R11.1 -8.04,-11.239 -7.544,-11.735 -5.69,-11.735 -5.436,-11.481 -5.436,-10.846 -4.851,-10.262 -4.115,-10.262 -2.729,-8.876 2.834,-8.876 5.436,-6.274 5.436,-5.486 5.862,-5.06 U1.3 8.377,-5.06 8.839,-4.597 R33.2@9.373,-4.597
  TopLayer w0.5: R11.1 C7.2
UC: C11.2 R4.1 R12.1 R32.2 U1.2 | length 25.5
  TopLayer w0.25: R4.1 -8.895,-12.46 -8.06,-12.46 R12.1 ; C11.2@-8.04,-13.575 -7.417,-14.199 -3.302,-14.199 -3.15,-14.046 -3.15,-10.033 -2.442,-9.326 3.02,-9.326 6.561,-5.785 7.365,-5.785 U1.2 9.022,-5.71 9.095,-5.637 9.248,-5.637 R32.2@9.373,-5.512
  TopLayer w0.5: C11.2 R12.1
UDC: C2.1 R15.2 R17.1 U1.10 | length 4.3
  TopLayer w0.4: U1.10 8.687,-0.51 8.998,-0.51 9.31,-0.51
  TopLayer w0.5: C2.1@8.992,-0.559 9.31,-0.559 R17.1 10.36,-0.56 R15.2
VBUS: C1.2 C10.2 C29.1 D11.1 pad.1@11.798,13.64 pad.3 R15.1 R16.1 R18.1 R22.1 R23.1 SW1.1 SW1.2 U2.3 U3.3 U4.3 U6.2 | length 251.9
  TopLayer w0.4: U4.3@-11.582,-5.222 -10.98,-5.222 ; U3.3@-11.557,0.366 -9.83,0.366 -9.627,0.366 -9.553,0.44 -9.474,0.518 ; U4.3 -10.991,-5.232 -10.98,-5.222 ; U3.3 -10.991,0.371 -10.786,0.575 ; U2.3 -10.991,6.263 ; -10.773,6.481 -10.991,6.263 ; -10.49,-4.674 -10.49,-4.732 -10.98,-5.222 ; -10.414,6.296 -10.447,6.263 -10.991,6.263 ; -8.382,-5.182 -8.422,-5.222 -10.98,-5.222
  TopLayer w0.5: v1@-9.751,0.44 -9.553,0.44 R18.1 -8,0.712 -8.764,0.712 v1@-9.119,1.067 ; v1@-9.681,6.192 -8.608,6.192 ; -9.576,6.756 -9.51,6.691 v1@-9.259,6.44 ; v1@-9.462,6.44 v1@-9.259,6.44 ; v1@-9.22,-5.182 -8.382,-5.182 -8.054,-5.182 -8.04,-5.168 -8.04,-4.76 -8.651,-4.76 ; v1(-9.119,-4.293) -8.651,-4.76 ; v1@-9.058,-4.76 -8.651,-4.76 ; v1@-8.989,7.085 -8.979,7.075 v1@-8.979,6.44 ; v1(-8.966,6.335) -8.979,6.348 v1@-8.979,6.44 ; v1@-8.89,7.074 v1@-8.89,6.44 ; R22.1@-8.04,6.262 R22.1 -8.192,6.192 -8.608,6.192 ; R15.1 14.442,-1.56 14.589,-1.413 14.808,-1.194 14.84,-1.162 14.84,-0.813 14.84,2.28 ; v1@-9.259,6.44 v1@-8.979,6.44 ; v1@-8.979,6.44 v1@-8.89,6.44 ; v1@-8.89,6.44 -8.856,6.44 -8.608,6.192
  TopLayer w0.7: -10.541,0.52 -10.541,1.309 ; -10.541,6.296 -10.541,7.085 ; -10.516,-5.056 -10.49,-5.031 -10.49,-4.732 ; -10.49,-4.674 -10.49,-4.293 -10.287,-4.293 ; -10.287,-5.056 -10.287,-4.293 ; -10.236,0.52 -10.236,1.307 ; -10.06,6.691 v1@-9.703,6.691 ; -9.346,6.691 -9.51,6.691 v1@-9.703,6.691 ; v1@-9.12,1.524 -10.516,1.524 -10.541,1.499 -10.541,1.309 ; v1@-9.058,-4.76 v1@-9.119,-4.76 ; v1@-8.989,7.085 v1@-9.703,7.085 ; -10.541,1.309 -10.539,1.307 -10.236,1.307 ; -10.287,-4.293 v1(-9.83,-4.293) ; -10.236,1.307 -10.236,1.309 -9.12,1.309 v1(-9.119,1.307) ; -10.236,1.307 v1(-9.83,1.307) ; -9.83,-4.687 v1(-9.83,-4.293) ; -9.83,-4.687 v1(-9.83,-5.082) v1(-9.119,-5.082) v1@-9.119,-4.76 ; -9.83,-4.687 -9.757,-4.76 v1@-9.119,-4.76 ; v1(-9.83,-4.293) v1(-9.119,-4.293) v1@-9.119,-4.76 ; -9.83,0.913 v1(-9.83,1.307) ; -9.83,0.913 v1(-9.83,0.518) -9.474,0.518 v1(-9.119,0.518) v1@-9.119,1.067 ; -9.83,0.913 -9.676,1.067 v1@-9.119,1.067 ; v1(-9.83,1.307) v1(-9.119,1.307) ; v1@-9.703,6.691 v1@-9.703,7.085 ; v1@-9.703,6.691 -9.703,6.296 -10.414,6.296 -10.414,7.085 v1@-9.703,7.085 ; v1@-9.119,1.067 v1(-9.119,1.307)
  TopLayer w0.8: SW1.2@9.094,12.379 SW1.2 12.506,12.379 v1(12.979,12.852) ; v1(10.719,14.376) 10.852,14.51 11.908,14.51 pad.1@12.574,13.844 ; v1(11.43,13.64) 11.798,13.64 v1(12.167,13.64) ; v1(11.43,14.402) 11.43,14.376 v1(12.167,13.64) ; 14.808,-1.397 14.808,-1.194 14.808,3.023 ; 14.84,-1.162 15.837,-0.165 15.837,4.039 ; 14.84,-0.813 15.323,-0.33 15.119,-0.127 15.119,3.321 ; v1(16.358,8.687) v1(16.358,7.963) 16.358,7.239 ; v1(12.167,13.64) 12.37,13.64 pad.1@12.574,13.844 ; pad.1@12.574,13.844 v1@12.979,13.438 ; v1(12.979,12.852) v1(12.192,12.852) 9.627,12.852 9.55,12.929 12.47,12.929 v1@12.979,13.438 ; v1(12.979,12.852) v1@12.979,13.438 ; 14.808,3.023 14.821,3.023 15.119,3.321 ; 14.808,3.023 14.306,2.52 C1.2 12.339,2.52 12.339,3.866 10.053,3.866 10.053,0.767 12.466,0.767 12.466,-1.413 14.589,-1.413 15.859,-1.413 ; 15.119,3.321 15.837,4.039 ; 15.837,4.039 15.837,6.845 16.231,7.239 16.358,7.239 ; 15.859,-1.413 15.859,-0.524 16.358,-0.025 ; 15.859,-1.413 16.358,-0.914 16.358,-0.025 ; 16.358,-0.025 16.358,7.239
  BottomLayer w0.3: R23.1@10.72,0.329 R23.1@10.77,0.279 ; R23.1@10.744,0.229 10.77,0.254 R23.1@10.77,0.279 ; 12.44,7.88 12.198,7.88 12.198,5.086 10.82,3.708 R23.1 R23.1@10.77,0.279
  BottomLayer w0.5: 10.08,13.45 10.951,13.45 11.108,13.293 11.523,12.878 C29.1@12.44,11.961
  BottomLayer w0.7: v1@-9.119,-5.182 v1@-9.83,-5.182 ; -9.119,9.601 -6.68,12.04 ; -8.642,9.982 -7.925,9.982 ; -8.458,-5.182 -7.722,-5.182 -7.722,-3.505 ; -8.458,8.915 -8.458,9.449 -7.925,9.982 ; -8.204,6.259 -7.722,6.742 ; -7.864,-4.993 -7.864,-3.647 ; -7.864,5.918 -7.864,5.359 ; -7.595,5.359 -7.722,5.359 ; -7.569,12.04 -9.83,9.779 ; -6.02,14.529 -9.83,10.719 -9.83,9.779 ; -5.969,11.938 -7.722,10.185 ; -5.918,9.982 -7.442,9.982 ; -5.385,12.04 -7.442,9.982 ; -5.334,-5.537 -9.83,-5.537 v1@-9.83,-5.182 ; -5.334,-5.512 -5.334,5.89 -6.931,5.89 -7.722,6.68 ; v1@-9.83,-5.182 v1(-9.83,-5.082) v1(-9.83,-4.293) -9.83,-3.937 -8.153,-3.937 -7.864,-3.647 ; -9.83,9.779 -9.83,5.359 -8.676,5.359 ; -8.676,5.359 -7.864,5.359 ; -8.676,5.359 -7.864,4.547 ; -7.925,9.982 -7.722,9.982 ; -7.925,9.982 -7.722,10.185 ; -7.864,-3.647 -7.864,-0.229 ; -7.864,-3.647 -7.722,-3.505 ; -7.864,-0.229 -7.864,2.007 ; -7.864,-0.229 -8.168,0.076 -9.83,0.076 v1(-9.83,0.518) v1(-9.83,1.307) -9.83,1.651 -8.219,1.651 -7.864,2.007 ; -7.864,2.007 -7.864,4.547 ; -7.864,4.547 -7.864,5.359 ; -7.864,5.359 -7.722,5.359 ; -7.722,-3.505 -7.722,5.359 ; -7.722,5.359 -7.722,6.68 ; -7.722,6.68 -7.722,6.742 ; -7.722,6.742 -7.722,9.703 ; -7.722,9.703 -7.722,9.982 ; -7.722,9.703 -7.442,9.982 ; -7.722,9.982 -7.722,10.185 ; -7.722,9.982 -7.442,9.982
  BottomLayer w0.8: -6.375,10.16 -3.556,12.979 ; -6.02,14.529 -1.981,14.529 -1.194,13.741 ; -5.791,10.16 -2.565,13.386 ; -2.505,12.709 -2.337,12.878 ; 2.87,12.878 v1(11.43,12.878) 11.523,12.878 v1@11.963,12.878 ; v1@11.532,13.31 v1@11.963,12.878 ; v1@12.243,12.878 v1@11.963,12.878 ; C29.1 12.598,11.72 C29.1@12.44,11.878 ; v1@12.712,13.741 14.351,12.103 D11.1@14.351,9.754 ; 15.424,10.702 15.424,7.88 12.44,7.88 C29.1@12.44,11.878 ; v1@11.963,12.878 12.44,12.401 12.44,11.961 C29.1@12.44,11.878
  other v1: -9.728,6.36 -9.728,7.072 -8.992,7.072 10.719,12.903 10.719,13.64 12.878,13.64
VIN: C8.2 J1.2 J1.5 pad.2@12.548,-8.712 R29.1 R39.1 U5.3 | length 80.3
  TopLayer w0.25: R39.1@10.36,-6.502 12.344,-6.502 12.675,-6.833 12.675,-8.585 v1(12.548,-8.712)
  BottomLayer w0.25: U5.3 12.979,-4.14 13.208,-4.14 13.411,-4.343 14.072,-5.004 14.224,-5.004 15.443,-5.004 15.748,-5.004 15.837,-5.093 15.913,-5.169 16.017,-5.273 16.053,-5.309 16.182,-5.438 ; R29.1 R29.1@16.864,-6.12 ; 16.182,-5.438 R29.1@16.37,-5.626 ; 16.182,-5.438 R29.1@16.37,-5.626 ; R29.1@16.37,-5.626 R29.1@16.864,-6.12 ; R29.1@16.37,-5.626 R29.1@16.864,-6.12 ; R29.1@16.37,-5.626 R29.1@16.864,-6.12
  BottomLayer w0.3: C8.2@12.979,-4.216 13.767,-5.004 14.044,-5.004 ; C8.2 13.397,-4.357 14.044,-5.004 ; C8.2@13.487,-4.267 14.134,-4.914 14.224,-5.004 ; 14.072,-5.004 14.044,-5.004 ; 15.443,-5.004 15.977,-5.537 ; 15.748,-5.004 15.926,-5.004 ; 16.106,-5.184 16.195,-5.273 ; R29.1@16.459,-5.537 16.271,-5.349 16.195,-5.273 ; R29.1@16.612,-5.537 16.535,-5.461 16.347,-5.273 ; 15.926,-5.004 16.002,-5.08 16.195,-5.273 ; 15.926,-5.004 16.078,-5.004 16.271,-5.197 ; 16.271,-5.197 16.347,-5.273 ; 16.271,-5.197 16.347,-5.273
  BottomLayer w0.6: -1.964,-15.138 -1.752,-14.927 -1.583,-14.757 ; -1.964,-14.715 -1.922,-14.757 -1.583,-14.757 ; -1.52,-14.355 -1.118,-14.757 ; 1.52,-14.372 1.135,-14.757 ; 1.844,-14.757 1.52,-14.757 1.135,-14.757 ; -1.583,-14.757 -1.118,-14.757 ; -1.118,-14.757 1.135,-14.757
  BottomLayer w0.8: -2.563,-17.752 -2.563,-15.314 ; -1.964,-18.239 -1.964,-15.138 -1.964,-14.91 ; J1.2 -1.52,-14.271 -1.964,-14.715 ; J1.5 1.52,-14.372 1.874,-14.727 2.515,-15.367 2.515,-17.663 1.905,-18.273 ; 2.057,-14.859 6.426,-14.859 ; 4.619,-17.958 4.304,-18.273 1.905,-18.273 ; 15.951,-8.052 16.307,-7.696 16.51,-7.493 R29.1@16.51,-6.245 ; 16.017,-5.273 16.053,-5.273 ; 16.053,-5.24 16.053,-5.273 ; 16.408,-8.433 17.105,-7.736 R29.1@17.105,-6.263 ; 17.816,-5.273 16.347,-5.273 16.195,-5.273 16.053,-5.273 ; -2.845,-17.678 -2.845,-15.596 ; -2.845,-17.678 -2.25,-18.273 ; -2.845,-17.678 -2.845,-18.273 -2.25,-18.273 ; -2.845,-15.596 -2.563,-15.314 ; -2.845,-15.596 -2.845,-14.91 -2.159,-14.91 ; -2.563,-15.314 -2.159,-14.91 ; -2.25,-18.273 1.905,-18.273 ; -2.159,-14.91 -1.964,-14.715 ; -2.159,-14.91 -1.964,-14.91 ; -1.964,-14.91 -1.964,-14.715 ; 6.426,-14.859 6.604,-14.859 7.747,-13.716 7.747,-13.538 ; 6.426,-14.859 7.747,-13.538 ; 7.747,-13.538 7.747,-10.846 10.541,-8.052 15.443,-8.052 15.697,-7.798 16.053,-7.442 16.053,-5.626 16.053,-5.309 16.053,-5.273
pads on no net: J1.3 J1.4 S1.4
copper on no net: | length 37.7
  BottomLayer w0.254: -10.7,-12.1 ccw(c-12.7,-12.1) -10.7,-12.1 ; 2,16.5 ccw(c0,16.5) 2,16.5 ; 14.7,-12.1 ccw(c12.7,-12.1) 14.7,-12.1

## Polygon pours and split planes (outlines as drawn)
GND on TopLayer "GND_L01_P017" (hatched 90Degree grid 0.5 track 0.5, remove dead copper, pour order 17): 1.905,5.944 0.787,7.061 0.787,7.087 -2.464,7.087 -2.972,7.595 -2.972,13.995 -2.413,14.554 -1.448,14.554 -0.508,13.614 1.676,13.614 2.464,14.402 2.464,16.129 3.124,16.789 7.442,16.789 8.153,16.078 8.153,11.227 7.747,10.82
GND on TopLayer "TopLayer-GND" (hatched 90Degree grid 0.8 track 0.8, remove dead copper, pour order 0): -2.362,-13.894 6.401,-13.894 10.36,-9.935 10.36,-7.087 3.48,-7.087 3.48,-9.957 -2.362,-9.957
GND on TopLayer "TopLayer-GND 1" (hatched 90Degree grid 0.8 track 0.8, remove dead copper, pour order 2): 14.554,4.801 8.857,4.801 8.857,3.658 7.841,3.658 6.647,4.851 6.368,5.131 3.803,5.131 3.803,2.54 2.075,2.54 2.075,11.176 14.554,11.176
PHASEC on TopLayer "TopLayer-PHASEC" (hatched 90Degree grid 0.7 track 0.7, remove dead copper, pour order 4): -12.495,4.472 -12.495,14.656 -15.062,14.656 -17.704,12.014 ccw(c-17.704,11.532) -18.186,11.532 -18.186,4.472
GND on BottomLayer "BottomLayer-GND" (hatched 90Degree grid 0.6 track 0.6, remove dead copper, pour order 6): 0.457,10.414 0.457,4.14 -4.394,4.14 -4.394,-6.909 -7.391,-6.909 -7.391,-14.072 5.461,-14.072 6.315,-13.217 6.315,-9.957 9.287,-6.985 9.042,-6.985 9.271,-6.756 9.271,10.414
VIN on BottomLayer "BottomLayer-VIN" (hatched 90Degree grid 0.9 track 0.9, remove dead copper, pour order 10): 17.816,-5.273 17.816,-8.738 8.113,-18.44 2.54,-18.44 2.54,-14.859 6.96,-14.859 7.747,-14.072 7.747,-10.49 10.185,-8.052 16.078,-8.052 16.078,-5.375 17.816,-5.375
VBUS on BottomLayer "BottomLayer-VBUS" (hatched 90Degree grid 0.9 track 0.9, remove dead copper, pour order 8): 12.598,7.925 17.323,7.925 17.323,9.931 10.668,16.586 -6.553,16.586 -6.553,13.538 -8.103,11.989 -4.826,11.989 2.667,11.989 4.039,13.36 12.598,13.36 12.598,8.128
NetR19_1 on BottomLayer "BottomLayer-NetR19_1" (hatched 90Degree grid 0.7 track 0.7, remove dead copper, pour order 12): -10.744,11.201 -7.645,14.3 -7.645,17.424 -12.116,17.424 -12.116,11.227 -10.744,11.227
PHASEA on BottomLayer "BottomLayer-PHASEA" (hatched 90Degree grid 0.7 track 0.7, remove dead copper, pour order 14): -13.335,-3.226 -13.335,-10.49 -15.164,-12.319 -18.263,-9.22 -18.415,-9.068 -18.415,-3.226
PHASEC on BottomLayer "BottomLayer-PHASEC" (hatched 90Degree grid 0.7 track 0.7, remove dead copper, pour order 16): -14.046,3.226 -14.046,14.427 -14.681,14.427 -18.339,10.77 -18.339,3.226

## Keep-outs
KeepOutLayer:
  circle w0.127: c0,16.5 r1.1
  circle w0.127: c-12.7,-12.1 r1.1
  circle w0.127: c12.7,-12.1 r1.1
  lines w0.127: 10.535,-16.41 ccw(c0,0) 18.382,-6.509
  lines w0.254: -19.03,4.257 cw(c0,0) -4.387,19 4.387,19 cw(c0,0) 19,4.387 19,-4.387 ; -19.025,-4.387 -19.025,4.387 ; -19.024,-4.281 ccw(c0,0) -4.387,-19 4.387,-19 ccw(c0,0) 19,-4.388

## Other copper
TopLayer:
  rectangle net VBUS: 12.339,-1.162 14.84,2.52
  rectangle net VBUS: 10.053,1.016 12.421,3.866
  rectangle net GND: 8.596,-2.384 10.36,-1.56
  rectangle net NetR19_1: -6.401,7.163 -4.216,9.347
  rectangle net PHASEA: -15.951,-7.442 -12.497,-3.227
  rectangle net VBUS: 8.712,12.601 11.633,14.961
  rectangle net PHASEB: -17.719,-2.057 -12.509,2.5
  rectangle net NetR19_1: -11.54,8.56 -4.445,14.58
BottomLayer:
  rectangle net NetC9_2: 14.961,-4.204 17.894,-1.651
  rectangle net NetD11_2: 13.208,3.785 17.457,6.629
  rectangle net VBUS: -9.83,5.461 -7.864,10.719
  rectangle net NetR19_1: -12.141,-9.398 -8.458,-6.629
  rectangle net NetR19_1: -10.744,-2.692 -8.764,-1.154
  rectangle net VBUS: -9.83,-5.537 -5.334,-3.937
  rectangle net VBUS: -7.722,-4.369 -5.334,6.172
  rectangle net VBUS: -9.83,0.178 -7.864,1.651
  rectangle net NetR19_1: -10.744,2.718 -8.814,4.47
  rectangle net PHASEB: -18.323,-2.616 -13.081,2.87

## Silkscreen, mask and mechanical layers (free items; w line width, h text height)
TopOverlay:
  circle w0.254: c-4.496,16.916 r1.414
  circle w0.254: c9.322,-14.783 r1.414
  circle w0.254: c0,16.5 r2
  circle w0.254: c-12.7,-12.1 r2
  circle w0.254: c12.7,-12.1 r2
  text "B+" at 2.24,12.83 h1.2
  text "B-" at 2.22,9.49 h1.2
  text "U" at -16.993,6.655 h1.2
  text "W" at -16.993,-2.413 h1.2
  text "V" at -16.789,-7.849 h1.2
BottomOverlay:
  circle w0.254: c0,16.5 r2
  circle w0.254: c-12.7,-12.1 r2
  circle w0.254: c12.7,-12.1 r2
  text "nanocorechip.com" at 4.36,13.36 h1.4
  text "VCC" at 4.648,4.011 h0.4 r90
  text "CLK" at -1.2,3.98 h0.4 r90
  text "DAT" at 1.02,3.98 h0.4 r90
  text "RST" at -3.2,3.96 h0.4 r90
  text "GND" at 2.88,3.96 h0.4 r90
